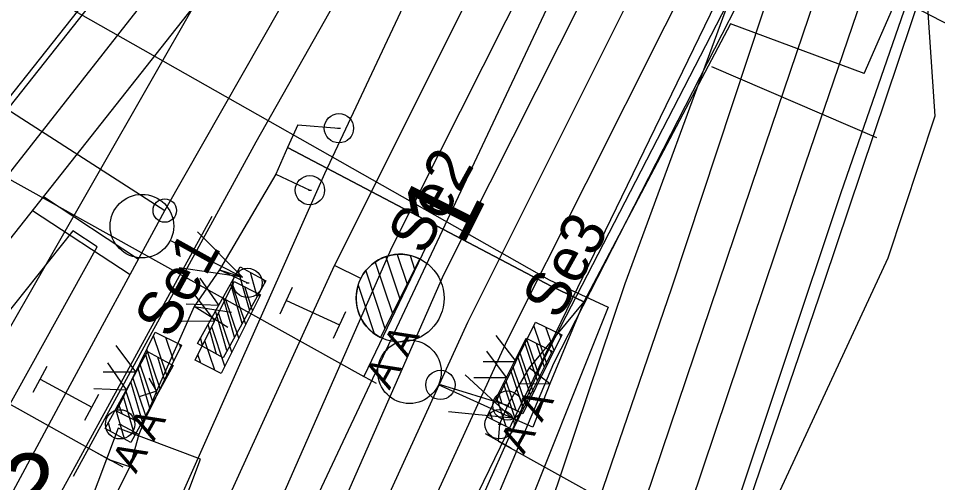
# Model space of a CAD drawing. Extents: x -598638 to -597933, y -1164002 to -1161904.
# Drawn here: x -598211.72 to -598180.34, y -1162957.08 to -1162941.24 of the extents above; entities that cross this region are included whole.
import ezdxf

# ---------------------------------------------------------------- set-up
doc = ezdxf.new("R2010")
doc.units = 0
for name, color, linetype in [('Vrstva 1', 7, 'Continuous'), ('Vrstva 17', 7, 'Continuous'), ('Vrstva 2', 7, 'Continuous'), ('Vrstva 25', 7, 'Continuous'), ('Vrstva 26', 7, 'Continuous'), ('Vrstva 28', 7, 'Continuous'), ('Vrstva 3', 7, 'Continuous'), ('Vrstva 31', 7, 'Continuous'), ('Vrstva 35', 7, 'Continuous'), ('Vrstva 4', 7, 'Continuous'), ('Vrstva 44', 7, 'Continuous'), ('Vrstva 51', 7, 'Continuous'), ('Vrstva 6', 7, 'Continuous'), ('Vrstva 63', 7, 'Continuous'), ('Vrstva 7', 7, 'Continuous')]:
    doc.layers.add(name, color=color, linetype=linetype)

msp = doc.modelspace()

# ---------------------------------------------------------------- linework, layer by layer
at = {"layer": 'Vrstva 1'}
msp.add_line((-598268.878, -1162907.772), (-598206.72, -1162947.797), dxfattribs=at)
for points in [[(-598245.185, -1163146.686), (-598244.89, -1163128.996), (-598244.069, -1163113.383), (-598243.892, -1163111.402), (-598242.508, -1163095.903), (-598240.221, -1163078.173), (-598237.7, -1163063), (-598234.456, -1163047.036), (-598230.819, -1163031.867), (-598224.044, -1163008.196), (-598218.147, -1162990.962), (-598212.612, -1162976.381), (-598210.162, -1162970.38), (-598207.127, -1162963.269), (-598201.66, -1162951.286), (-598200.923, -1162949.67), (-598193.375, -1162934.568), (-598185.535, -1162920.228)], [(-598240.169, -1163146.755), (-598239.921, -1163130.309), (-598239.07, -1163113.566), (-598238.926, -1163111.785), (-598238.259, -1163103.539), (-598237.54, -1163096.536), (-598235.247, -1163078.679), (-598233.075, -1163065.413), (-598229.628, -1163048.216), (-598226.08, -1163033.339), (-598219.335, -1163009.739), (-598213.514, -1162992.625), (-598208.094, -1162978.373), (-598205.572, -1162972.188), (-598202.745, -1162965.549), (-598196.38, -1162951.607), (-598188.854, -1162936.558), (-598181.238, -1162922.581)], [(-598180.286, -1162928.035), (-598182.126, -1162933.482), (-598183.238, -1162936.76), (-598184.095, -1162939.282), (-598186.438, -1162946.204), (-598190.315, -1162957.646), (-598194.225, -1162969.204), (-598198.163, -1162980.824), (-598202.116, -1162992.486)], [(-598227.645, -1162968.564), (-598218.383, -1162956.84), (-598218.042, -1162956.408), (-598203.893, -1162938.499)], [(-598206.72, -1162947.797), (-598202.083, -1162939.655)], [(-598252.219, -1163108.544), (-598251.499, -1163095.121), (-598249.615, -1163076.345), (-598247.361, -1163061.217), (-598244.383, -1163046.003), (-598242.664, -1163039.018), (-598240.128, -1163028.714), (-598235.674, -1163014.439), (-598232.556, -1163004.447), (-598225.931, -1162987.141), (-598216.898, -1162967.125), (-598213.283, -1162959.931), (-598210.092, -1162954.031), (-598206.72, -1162947.797)]]:
    msp.add_lwpolyline(points, dxfattribs=at)
msp.add_circle((-598206.72, -1162947.797), 0.4, dxfattribs=at)
at = {"layer": 'Vrstva 17'}
msp.add_lwpolyline([(-598160.869, -1162916.03), (-598165.61, -1162912.687), (-598173.226, -1162925.769), (-598179.204, -1162936.08), (-598180.398, -1162938.876), (-598184.227, -1162950.256), (-598188.104, -1162961.627), (-598191.911, -1162973.022), (-598198.535, -1162970.746), (-598204.125, -1162984.71), (-598208.617, -1162995.882), (-598214.208, -1163009.83), (-598215.031, -1163012.689), (-598218.215, -1163027.367), (-598221.453, -1163042.038), (-598223.962, -1163053.782), (-598226.517, -1163065.417), (-598227.975, -1163080.383)], dxfattribs=at)
at = {"layer": 'Vrstva 2'}
for p, q in [((-598199.357, -1162952.13), (-598198.016, -1162949.446)), ((-598198.016, -1162949.446), (-598199.357, -1162952.13)), ((-598199.178, -1162949.374), (-598198.698, -1162950.811)), ((-598198.782, -1162949.294), (-598198.445, -1162950.305)), ((-598198.348, -1162949.33), (-598198.192, -1162949.799)), ((-598200.028, -1162950.117), (-598200.923, -1162949.67)), ((-598199.538, -1162949.557), (-598198.951, -1162951.317)), ((-598199.86, -1162949.858), (-598199.204, -1162951.823)), ((-598200.118, -1162950.346), (-598199.567, -1162951.998))]:
    msp.add_line(p, q, dxfattribs=at)
msp.add_lwpolyline([(-598200.923, -1162949.67), (-598193.375, -1162934.568), (-598185.535, -1162920.228)], dxfattribs=at)
msp.add_circle((-598198.687, -1162950.788), 1.5, dxfattribs=at)
msp.add_arc((-598198.687, -1162950.788), 1.5, 63.444, 243.444, dxfattribs=at)
at = {"layer": 'Vrstva 25'}
for p, q in [((-598200.823, -1162944.988), (-598200.723, -1162944.988)), ((-598201.816, -1162947.102), (-598201.716, -1162947.102)), ((-598203.944, -1162950.266), (-598203.844, -1162950.266)), ((-598197.361, -1162953.749), (-598197.261, -1162953.749)), ((-598195.074, -1162954.452), (-598194.974, -1162954.452)), ((-598208.297, -1162955.095), (-598208.197, -1162955.095)), ((-598195.34, -1162955.091), (-598195.24, -1162955.091))]:
    msp.add_line(p, q, dxfattribs=at)
for centre in [(-598200.773, -1162944.988), (-598201.766, -1162947.102), (-598203.894, -1162950.266), (-598197.311, -1162953.749), (-598195.024, -1162954.452), (-598208.247, -1162955.095), (-598195.29, -1162955.091)]:
    msp.add_circle(centre, 0.5, dxfattribs=at)
at = {"layer": 'Vrstva 26'}
msp.add_lwpolyline([(-598211.382, -1162940.065), (-598193.601, -1162950.161), (-598191.584, -1162951.092), (-598198.026, -1162967.205), (-598208.688, -1162993.504), (-598209.03, -1162994.474), (-598214.707, -1163009.33), (-598218.558, -1163024.082), (-598220.34, -1163031.684), (-598220.756, -1163034.417), (-598224.218, -1163049.876), (-598227.646, -1163065.71), (-598228.067, -1163068.213), (-598230.531, -1163097), (-598231.676, -1163107.807), (-598231.723, -1163120.907), (-598232.574, -1163129.537), (-598231.426, -1163150.759)], dxfattribs=at)
at = {"layer": 'Vrstva 28'}
for p, q in [((-598203.823, -1162951.19), (-598204.21, -1162949.829)), ((-598203.566, -1162950.727), (-598203.798, -1162949.912)), ((-598204.081, -1162951.654), (-598204.468, -1162950.294)), ((-598203.958, -1162951.682), (-598204.406, -1162950.34)), ((-598203.721, -1162951.207), (-598203.991, -1162950.403)), ((-598203.308, -1162950.263), (-598203.335, -1162950.168)), ((-598203.485, -1162950.733), (-598203.516, -1162950.639)), ((-598204.339, -1162952.117), (-598204.727, -1162950.758)), ((-598204.194, -1162952.158), (-598204.643, -1162950.816)), ((-598204.597, -1162952.58), (-598204.984, -1162951.22)), ((-598204.431, -1162952.632), (-598204.88, -1162951.29)), ((-598204.952, -1162952.701), (-598205.243, -1162951.684)), ((-598204.667, -1162953.106), (-598205.116, -1162951.765)), ((-598193.668, -1162953.059), (-598194.123, -1162951.719)), ((-598193.433, -1162952.584), (-598193.707, -1162951.78)), ((-598206.648, -1162953.411), (-598207.101, -1162952.071)), ((-598206.413, -1162952.935), (-598206.684, -1162952.131)), ((-598205.416, -1162952.444), (-598205.5, -1162952.147)), ((-598205.016, -1162953.243), (-598205.353, -1162952.24)), ((-598193.998, -1162953.613), (-598194.443, -1162952.271)), ((-598193.903, -1162953.535), (-598194.357, -1162952.196)), ((-598193.2, -1162952.108), (-598193.231, -1162952.015)), ((-598206.882, -1162953.886), (-598207.336, -1162952.546)), ((-598206.178, -1162952.459), (-598206.209, -1162952.366)), ((-598193.76, -1162953.139), (-598194.027, -1162952.334)), ((-598193.522, -1162952.665), (-598193.553, -1162952.572)), ((-598206.974, -1162954.076), (-598207.368, -1162952.719)), ((-598206.718, -1162953.612), (-598206.955, -1162952.798)), ((-598205.491, -1162953.007), (-598205.589, -1162952.714)), ((-598194.235, -1162954.088), (-598194.681, -1162952.746)), ((-598194.138, -1162954.01), (-598194.592, -1162952.671)), ((-598207.23, -1162954.542), (-598207.624, -1162953.184)), ((-598207.117, -1162954.36), (-598207.571, -1162953.022)), ((-598206.463, -1162953.147), (-598206.49, -1162953.053)), ((-598194.472, -1162954.562), (-598194.919, -1162953.22)), ((-598194.372, -1162954.486), (-598194.826, -1162953.147)), ((-598207.353, -1162954.837), (-598207.806, -1162953.496)), ((-598207.485, -1162955.006), (-598207.879, -1162953.648)), ((-598195.024, -1162954.452), (-598197.311, -1162953.749)), ((-598194.71, -1162955.036), (-598195.156, -1162953.694)), ((-598194.721, -1162954.625), (-598195.061, -1162953.622)), ((-598207.74, -1162955.471), (-598208.135, -1162954.112)), ((-598207.702, -1162954.975), (-598208.04, -1162953.973)), ((-598195.061, -1162955.172), (-598195.394, -1162954.168)), ((-598195.197, -1162954.39), (-598195.296, -1162954.098)), ((-598208.178, -1162954.74), (-598208.276, -1162954.448)), ((-598208.096, -1162955.593), (-598208.391, -1162954.578)), ((-598195.535, -1162954.935), (-598195.632, -1162954.642)), ((-598208.559, -1162955.339), (-598208.646, -1162955.042))]:
    msp.add_line(p, q, dxfattribs=at)
for points in [[(-598182.85, -1162943.114), (-598181.721, -1162940.54), (-598181.991, -1162939.535), (-598184.118, -1162939.174)], [(-598182.85, -1162943.114), (-598187.405, -1162941.424), (-598192.42, -1162950.91)], [(-598202.181, -1162944.87), (-598202.53, -1162945.64), (-598202.926, -1162946.559), (-598204.855, -1162949.82), (-598205.72, -1162951.07), (-598207, -1162953.96), (-598207.602, -1162955.437), (-598207.909, -1162956.541), (-598214.715, -1162969.968), (-598215.393, -1162971.231), (-598221.006, -1162968.851), (-598221.077, -1162967.697), (-598220.617, -1162965.35), (-598218.165, -1162961.552), (-598217.795, -1162959.839)], [(-598202.181, -1162944.87), (-598200.773, -1162944.988)], [(-598202.53, -1162945.64), (-598197.448, -1162948.316), (-598193.51, -1162950.39), (-598192.42, -1162950.91), (-598193.57, -1162953.71), (-598194.16, -1162955.19), (-598194.86, -1162954.88)], [(-598202.926, -1162946.559), (-598201.766, -1162947.102)], [(-598197.448, -1162948.316), (-598197.674, -1162948.761), (-598199.928, -1162953.462)], [(-598205.607, -1162952.338), (-598204.147, -1162949.716), (-598203.273, -1162950.202), (-598204.732, -1162952.824), (-598205.607, -1162952.338)], [(-598205.994, -1162950.978), (-598204.877, -1162951.027), (-598205.508, -1162950.104)], [(-598204.855, -1162949.82), (-598204.07, -1162950.07)], [(-598204.855, -1162949.82), (-598203.894, -1162950.266)], [(-598205.686, -1162952.909), (-598204.349, -1162950.224), (-598203.453, -1162950.67), (-598204.791, -1162953.356), (-598205.686, -1162952.909)], [(-598206.135, -1162951.569), (-598205.016, -1162951.567), (-598205.69, -1162950.673)], [(-598192.42, -1162950.91), (-598194.28, -1162953.17), (-598194.61, -1162953.72), (-598195.024, -1162954.452), (-598195.29, -1162955.091), (-598195.337, -1162955.666)], [(-598204.57, -1162951.79), (-598205.72, -1162951.07), (-598204.44, -1162951.27)], [(-598195.392, -1162954.294), (-598194.065, -1162951.603), (-598193.168, -1162952.045), (-598194.495, -1162954.736), (-598195.392, -1162954.294)], [(-598208.372, -1162954.643), (-598207.043, -1162951.954), (-598206.146, -1162952.397), (-598207.476, -1162955.087), (-598208.372, -1162954.643)], [(-598195.847, -1162952.955), (-598194.729, -1162952.949), (-598195.404, -1162952.058)], [(-598195.729, -1162954.837), (-598194.385, -1162952.155), (-598193.491, -1162952.603), (-598194.835, -1162955.285), (-598195.729, -1162954.837)], [(-598208.826, -1162953.303), (-598207.707, -1162953.299), (-598208.383, -1162952.407)], [(-598208.751, -1162955.233), (-598207.305, -1162952.605), (-598206.429, -1162953.087), (-598207.875, -1162955.715), (-598208.751, -1162955.233)], [(-598196.175, -1162953.495), (-598195.057, -1162953.496), (-598195.727, -1162952.601)], [(-598209.145, -1162953.875), (-598208.028, -1162953.92), (-598208.663, -1162952.999)], [(-598193.57, -1162953.71), (-598194.28, -1162953.17)], [(-598207.26, -1162953.52), (-598207, -1162953.96), (-598207.59, -1162954.16)], [(-598193.57, -1162953.71), (-598194.61, -1162953.72)], [(-598207.602, -1162955.437), (-598208.247, -1162955.095)], [(-598207.909, -1162956.541), (-598208.58, -1162956.318)]]:
    msp.add_lwpolyline(points, dxfattribs=at)
for points in [[(-598205.607, -1162952.338), (-598204.147, -1162949.716), (-598203.273, -1162950.202), (-598204.732, -1162952.824)], [(-598205.686, -1162952.909), (-598204.349, -1162950.224), (-598203.453, -1162950.67), (-598204.791, -1162953.356)], [(-598195.392, -1162954.294), (-598194.065, -1162951.603), (-598193.168, -1162952.045), (-598194.495, -1162954.736)], [(-598208.372, -1162954.643), (-598207.043, -1162951.954), (-598206.146, -1162952.397), (-598207.476, -1162955.087)], [(-598195.729, -1162954.837), (-598194.385, -1162952.155), (-598193.491, -1162952.603), (-598194.835, -1162955.285)], [(-598208.751, -1162955.233), (-598207.305, -1162952.605), (-598206.429, -1162953.087), (-598207.875, -1162955.715)]]:
    msp.add_lwpolyline(points, close=True, dxfattribs=at)
at = {"layer": 'Vrstva 3'}
for p, q in [((-598204.07, -1162950.07), (-598205.606, -1162948.519)), ((-598204.07, -1162950.07), (-598206.532, -1162948.824)), ((-598204.07, -1162950.07), (-598206.228, -1162949.751)), ((-598202.777, -1162951.326), (-598202.362, -1162950.416)), ((-598202.57, -1162950.871), (-598200.75, -1162951.701)), ((-598200.958, -1162952.156), (-598200.543, -1162951.246)), ((-598211.209, -1162953.995), (-598210.734, -1162953.115)), ((-598210.972, -1162953.555), (-598209.212, -1162954.507)), ((-598194.86, -1162954.88), (-598196.468, -1162953.404)), ((-598194.86, -1162954.88), (-598197.379, -1162953.752)), ((-598209.45, -1162954.947), (-598208.975, -1162954.067)), ((-598194.86, -1162954.88), (-598197.031, -1162954.664))]:
    msp.add_line(p, q, dxfattribs=at)
for centre in [(-598207.5, -1162948.328), (-598198.367, -1162953.302)]:
    msp.add_circle(centre, 1.084, dxfattribs=at)
at = {"layer": 'Vrstva 31'}
msp.add_lwpolyline([(-598153.447, -1162881.401), (-598158.917, -1162890.286), (-598163.962, -1162898.735), (-598165.887, -1162906.436), (-598166.192, -1162908.567), (-598166.64, -1162910.14), (-598167.818, -1162914.276), (-598168.011, -1162918.252), (-598168.382, -1162919.355), (-598171.993, -1162924.817), (-598180.701, -1162940.523), (-598180.438, -1162944.574), (-598182.04, -1162949.425), (-598187.501, -1162961.184)], dxfattribs=at)
at = {"layer": 'Vrstva 35'}
msp.add_line((-598188.058, -1162942.881), (-598182.422, -1162945.306), dxfattribs=at)
msp.add_lwpolyline([(-598192.42, -1162950.91), (-598193.51, -1162950.39), (-598197.448, -1162948.316), (-598202.53, -1162945.64)], dxfattribs=at)
at = {"layer": 'Vrstva 4'}
for points in [[(-598236.122, -1163097.625), (-598233.737, -1163078.205), (-598231.603, -1163064.919), (-598228.204, -1163048.211), (-598224.742, -1163033.919), (-598217.308, -1163008.105), (-598211.392, -1162991.093), (-598206.621, -1162978.751), (-598200.642, -1162964.474), (-598195.034, -1162952.232), (-598186.946, -1162936.115), (-598183.34, -1162929.36)], [(-598234.285, -1163099.455), (-598231.787, -1163078.342), (-598229.816, -1163067.198), (-598225.948, -1163048.912), (-598222.74, -1163035.209), (-598216.053, -1163011.484), (-598208.869, -1162991.272), (-598204.619, -1162979.312), (-598198.109, -1162964.057), (-598193.443, -1162953.005), (-598185.456, -1162937.387), (-598183.707, -1162933.568)]]:
    msp.add_lwpolyline(points, dxfattribs=at)
at = {"layer": 'Vrstva 44'}
for points in [[(-598295.758, -1163493.483), (-598278.118, -1163452.874), (-598264.209, -1163410.565), (-598254.468, -1163367.19), (-598248.62, -1163321.577), (-598253.497, -1163320.887), (-598249.615, -1163272.581), (-598247.635, -1163222.481), (-598247.486, -1163176.779), (-598247.442, -1163130.148), (-598244.014, -1163084.171), (-598235.33, -1163037.762), (-598224.817, -1163002.559), (-598219.379, -1163002.169), (-598206.652, -1162968.487), (-598191.401, -1162936.053), (-598173.754, -1162904.506), (-598155.689, -1162873.083), (-598136.14, -1162838.446), (-598116.776, -1162804.197)], [(-598214.433, -1163003.397), (-598199.219, -1162964.022), (-598185.65, -1162936.04), (-598163.291, -1162895.981), (-598150.219, -1162876.092), (-598140.441, -1162856.726), (-598110.998, -1162804.439)], [(-598217.579, -1162951.29), (-598196.167, -1162924.209), (-598178.917, -1162893.572), (-598182.378, -1162891.173)]]:
    msp.add_lwpolyline(points, dxfattribs=at)
at = {"layer": 'Vrstva 51'}
for points in [[(-598243.76, -1163139.382), (-598243.393, -1163128.836), (-598242.662, -1163113.52), (-598241.121, -1163096.732), (-598238.542, -1163077.297), (-598236.364, -1163063.881), (-598233.006, -1163047.35), (-598229.452, -1163032.186), (-598222.566, -1163008.635), (-598216.788, -1162991.447), (-598211.314, -1162977.141), (-598198.954, -1162949.031), (-598191.954, -1162935.136), (-598181.215, -1162915.654), (-598172.367, -1162900.092), (-598146.639, -1162854.694), (-598125.435, -1162817.431), (-598123.403, -1162813.873), (-598093.874, -1162762.323), (-598071.494, -1162722.83), (-598058.726, -1162701.732), (-598043.403, -1162678.606), (-598026.165, -1162652.845)], [(-598239.095, -1163097.092), (-598236.576, -1163077.501), (-598234.309, -1163064.254), (-598231.064, -1163047.867), (-598227.331, -1163032.522), (-598220.677, -1163009.309), (-598214.847, -1162992.197), (-598209.449, -1162977.846), (-598197.189, -1162949.981), (-598190.09, -1162935.876), (-598179.544, -1162916.618), (-598170.666, -1162900.915), (-598144.793, -1162855.5), (-598123.538, -1162818.503), (-598121.573, -1162814.996), (-598092.208, -1162763.361), (-598069.503, -1162724.253), (-598055.71, -1162703.114), (-598040.468, -1162680.627), (-598023.352, -1162655.056), (-598026.165, -1162652.845)], [(-598247.161, -1162992.683), (-598248.445, -1162991.682), (-598236.167, -1162974.65), (-598221.601, -1162956.026), (-598208.36, -1162939.293), (-598201.425, -1162930.155), (-598189.853, -1162912.957), (-598180.619, -1162896.952), (-598175.616, -1162888.402), (-598174.501, -1162888.256)], [(-598247.161, -1162992.683), (-598234.984, -1162975.74), (-598220.234, -1162956.982), (-598207.085, -1162940.213), (-598200.076, -1162931.081), (-598188.898, -1162913.557), (-598179.448, -1162896.986), (-598174.501, -1162888.256)], [(-598221.478, -1163080.78), (-598219.566, -1163067.136), (-598219.219, -1163065.098), (-598216.814, -1163053.054), (-598216.308, -1163050.154), (-598213.455, -1163037.18), (-598209.254, -1163020.993), (-598206.671, -1163012.257), (-598205.894, -1163009.286), (-598205.807, -1163008.944), (-598201.906, -1162996.551), (-598193.548, -1162971.953), (-598188.761, -1162957.834), (-598185.003, -1162946.673), (-598180.831, -1162934.422), (-598177.192, -1162923.967), (-598173.595, -1162914.671), (-598168.64, -1162904.115), (-598164.118, -1162895.651), (-598162.659, -1162896.444)], [(-598162.659, -1162896.444), (-598167.315, -1162905.247), (-598172.294, -1162915.543), (-598175.907, -1162924.588), (-598179.431, -1162935.039), (-598183.642, -1162947.197), (-598187.437, -1162958.573), (-598192.02, -1162972.557), (-598198.809, -1162992.788), (-598204.748, -1163011.314), (-598205.213, -1163012.907), (-598207.438, -1163020.452), (-598209.822, -1163028.442), (-598211.787, -1163036.541), (-598212.573, -1163039.781), (-598214.64, -1163049.347), (-598215.473, -1163053.325), (-598217.705, -1163064.512), (-598218.096, -1163067.37), (-598220.007, -1163080.081)], [(-598209.837, -1162956.862), (-598203.604, -1162945.446), (-598193.004, -1162926.731), (-598192.155, -1162927.156)], [(-598244.076, -1163096.672), (-598241.475, -1163076.865), (-598239.091, -1163062.576), (-598235.906, -1163046.679), (-598232.162, -1163031.147), (-598225.436, -1163007.609), (-598219.516, -1162990.586), (-598213.911, -1162975.868), (-598206.637, -1162958.627), (-598201.26, -1162946.534), (-598192.155, -1162927.156)], [(-598234.985, -1163097.818), (-598232.528, -1163078.41), (-598230.539, -1163066.595), (-598226.731, -1163048.661), (-598223.587, -1163035.053), (-598216.724, -1163011.435), (-598209.696, -1162991.235), (-598205.138, -1162979.218), (-598199.051, -1162964.673), (-598193.758, -1162952.835), (-598185.502, -1162936.812), (-598183.707, -1162933.568), (-598182.431, -1162929.818), (-598183.34, -1162929.36)], [(-598225.987, -1163079.977), (-598225.433, -1163075.24), (-598224.4, -1163068.446), (-598223.276, -1163062.974), (-598221.56, -1163053.654), (-598219.088, -1163041.864), (-598218.289, -1163038.506), (-598215.72, -1163028.247), (-598212.289, -1163016.175), (-598208.971, -1163004.649), (-598206.367, -1162996.288), (-598201.674, -1162982.251), (-598196.929, -1162967.908), (-598191.009, -1162950.285), (-598184.021, -1162931.293), (-598183.109, -1162931.599)], [(-598183.109, -1162931.599), (-598185.779, -1162939.427), (-598189.427, -1162950.443), (-598195.6, -1162968.473), (-598201.203, -1162984.962), (-598205.181, -1162996.978), (-598207.823, -1163005.387), (-598207.873, -1163005.495), (-598211.27, -1163016.966), (-598211.421, -1163017.483), (-598214.449, -1163028.785), (-598217.013, -1163039.126), (-598217.753, -1163042.541), (-598220.273, -1163054.386), (-598221.987, -1163063.395), (-598223.013, -1163069.069), (-598224.075, -1163075.616), (-598224.553, -1163080.356)], [(-598250.069, -1163094.383), (-598248.218, -1163076.729), (-598245.992, -1163061.387), (-598242.376, -1163043.691), (-598238.811, -1163029.107), (-598231.204, -1163004.927), (-598224.613, -1162987.744), (-598215.812, -1162968.252), (-598211.496, -1162959.672), (-598205.102, -1162947.99)], [(-598252.585, -1163090.153), (-598250.983, -1163076.012), (-598248.822, -1163061.344), (-598245.898, -1163045.485), (-598241.551, -1163027.791), (-598234.085, -1163003.948), (-598227.471, -1162986.56), (-598218.929, -1162967.779), (-598214.527, -1162958.931), (-598209.026, -1162949.032), (-598209.857, -1162948.487)], [(-598209.857, -1162948.487), (-598217.439, -1162958.007), (-598223.178, -1162965.17), (-598230.897, -1162975.026), (-598236.689, -1162982.935), (-598244.7, -1162994.275)]]:
    msp.add_lwpolyline(points, dxfattribs=at)
at = {"layer": 'Vrstva 6'}
for p, q in [((-598234.881, -1162934.012), (-598199.928, -1162953.462)), ((-598243.533, -1162936.868), (-598208.58, -1162956.318)), ((-598146.315, -1162959.151), (-598181.721, -1162940.54)), ((-598199.491, -1162953.705), (-598200.365, -1162953.219)), ((-598194.9, -1162955.909), (-598195.774, -1162955.423)), ((-598195.337, -1162955.666), (-598160.384, -1162975.116)), ((-598208.143, -1162956.561), (-598209.017, -1162956.075))]:
    msp.add_line(p, q, dxfattribs=at)
at = {"layer": 'Vrstva 63'}
msp.add_line((-598215.837, -1162958.494), (-598115.28, -1162782.61), dxfattribs=at)
at = {"layer": 'Vrstva 7'}
for p, q in [((-598210.861, -1162947.319), (-598207.616, -1162949.454)), ((-598211.234, -1162947.791), (-598207.903, -1162949.984))]:
    msp.add_line(p, q, dxfattribs=at)
msp.add_lwpolyline([(-598207.962, -1162958.567), (-598206.558, -1162959.096), (-598205.501, -1162956.288), (-598208.309, -1162955.231), (-598209.366, -1162958.039), (-598207.962, -1162958.567)], dxfattribs=at)

# ---------------------------------------------------------------- texts
at = {"layer": 'Vrstva 2'}
msp.add_text('1', height=2.5, rotation=63.4441, dxfattribs=at).set_placement((-598196.57, -1162949.089))
at = {"layer": 'Vrstva 6'}
for s, height, p in [('Se2', 1.5, (-598197.869, -1162949.371)), ('Se3', 1.5, (-598193.278, -1162951.575)), ('Se1', 1.5, (-598206.521, -1162952.227)), ('A A', 1, (-598199.054, -1162953.948)), ('A A', 1, (-598194.463, -1162956.152)), ('A A', 1, (-598207.706, -1162956.804))]:
    msp.add_text(s, height=height, rotation=60.9055, dxfattribs=at).set_placement(p)
at = {"layer": 'Vrstva 63'}
msp.add_text('642', height=2.4, dxfattribs=at).set_placement((-598215.837, -1162958.494))

doc.saveas('drawing.dxf')
